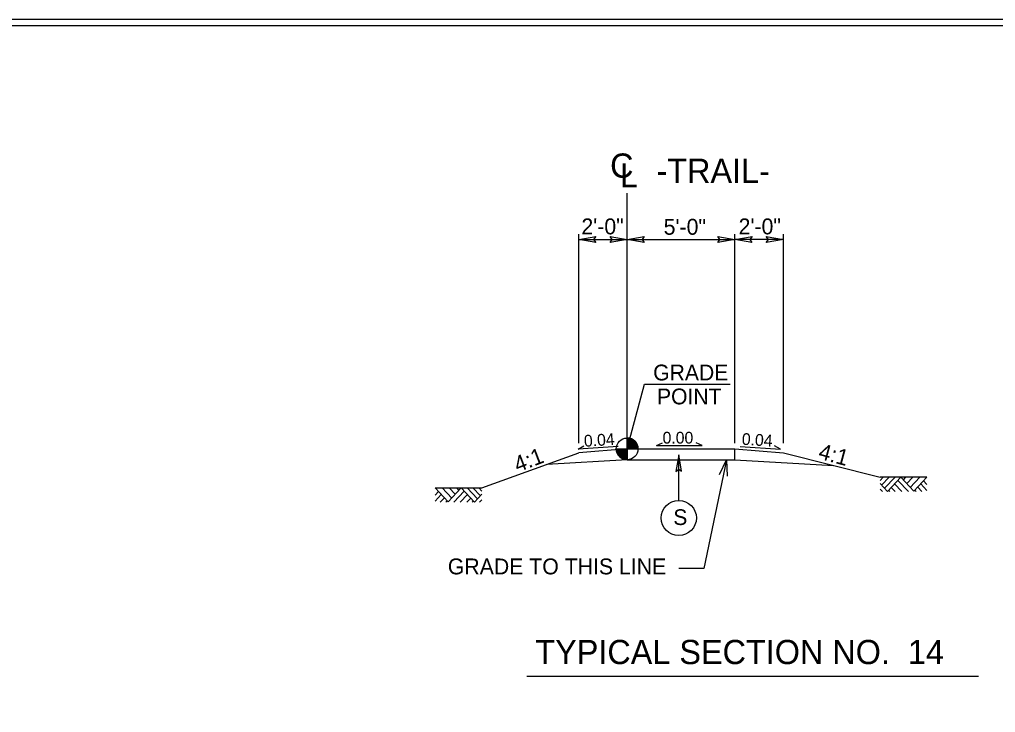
# Model space of a CAD drawing. Extents: x 1901670 to 1902225, y 193498 to 194278.
# Drawn here: x 1902063.51 to 1902103.81, y 193577.14 to 193605.77 of the extents above; entities that cross this region are included whole.
import ezdxf

# ---------------------------------------------------------------- set-up
doc = ezdxf.new("R2010")
doc.units = 0
for name, color, linetype in [('Old_Level_1', 7, 'Continuous'), ('Old_Level_11', 7, 'Continuous'), ('Old_Level_2', 7, 'Continuous'), ('Old_Level_20', 7, 'Continuous'), ('Prop Dimension', 7, 'Continuous'), ('Sheet Border Standard 30in CELL', 7, 'Continuous'), ('Sheet Plot Border Inside CELL', 7, 'Continuous'), ('Typical Hinge Slope Interstate CELL', 7, 'Continuous'), ('Typical Pavement Slope CELL', 7, 'Continuous'), ('Typical Terminator CELL', 7, 'Continuous'), ('Typical Text Grade Point CELL', 7, 'Continuous')]:
    doc.layers.add(name, color=color, linetype=linetype)

# ---------------------------------------------------------------- blocks, each defined once
blk = doc.blocks.new('TERMINATOR')
at = {"layer": 'Typical Terminator CELL'}
blk.add_lwpolyline([(-0.469, 0.081), (0, 0), (-0.471, -0.083), (-0.411, 0)], close=True, dxfattribs=at)

msp = doc.modelspace()

# ---------------------------------------------------------------- linework, layer by layer
at = {"layer": 'Old_Level_1'}
for p, q in [((1902088.596, 193588.03), (1902088.596, 193598.589)), ((1902086.596, 193588.262), (1902086.596, 193596.908)), ((1902093.046, 193588.262), (1902093.046, 193596.908)), ((1902095.046, 193588.262), (1902095.046, 193596.908)), ((1902086.596, 193596.68), (1902088.596, 193596.68)), ((1902095.046, 193596.68), (1902093.046, 193596.68)), ((1902088.596, 193588.03), (1902088.596, 193588.48)), ((1902086.569, 193588.017), (1902086.811, 193588.151)), ((1902088.228, 193588.125), (1902086.569, 193588.017)), ((1902088.596, 193588.03), (1902086.596, 193587.864)), ((1902088.146, 193588.03), (1902088.596, 193588.03)), ((1902088.595, 193587.58), (1902088.596, 193588.03)), ((1902088.596, 193588.03), (1902088.595, 193587.58)), ((1902088.596, 193587.585), (1902088.596, 193588.03)), ((1902089.046, 193588.03), (1902088.596, 193588.03)), ((1902088.596, 193588.03), (1902093.046, 193588.03)), ((1902089.81, 193588.167), (1902090.059, 193588.286)), ((1902089.81, 193588.167), (1902091.701, 193588.167)), ((1902090.039, 193588.167), (1902091.701, 193588.167)), ((1902091.701, 193588.167), (1902091.451, 193588.286)), ((1902093.046, 193587.585), (1902093.046, 193588.03)), ((1902093.046, 193588.03), (1902095.046, 193587.864)), ((1902093.267, 193588.125), (1902094.925, 193588.017)), ((1902094.925, 193588.017), (1902094.684, 193588.151)), ((1902088.596, 193587.585), (1902085.28, 193587.39)), ((1902088.596, 193587.585), (1902088.608, 193587.585)), ((1902088.596, 193587.585), (1902093.046, 193587.585)), ((1902093.046, 193587.585), (1902097.122, 193587.345)), ((1902095.046, 193587.864), (1902099.046, 193586.864)), ((1902099.172, 193586.864), (1902099.046, 193586.728)), ((1902099.41, 193586.864), (1902099.102, 193586.534)), ((1902099.657, 193586.864), (1902099.226, 193586.402)), ((1902099.895, 193586.863), (1902099.346, 193586.273)), ((1902100.208, 193586.267), (1902099.773, 193586.732)), ((1902100.438, 193586.28), (1902099.895, 193586.863)), ((1902100.091, 193586.864), (1902099.993, 193586.758)), ((1902100.389, 193586.864), (1902100.142, 193586.597)), ((1902100.684, 193586.864), (1902100.289, 193586.439)), ((1902100.975, 193586.858), (1902100.438, 193586.28)), ((1902100.975, 193586.56), (1902100.837, 193586.709)), ((1902080.667, 193586.417), (1902081.204, 193585.839)), ((1902080.957, 193586.423), (1902081.352, 193585.998)), ((1902081.204, 193585.839), (1902081.746, 193586.422)), ((1902081.252, 193586.423), (1902081.499, 193586.156)), ((1902081.55, 193586.423), (1902081.649, 193586.317)), ((1902081.746, 193586.422), (1902082.296, 193585.832)), ((1902081.985, 193586.423), (1902082.415, 193585.961)), ((1902082.232, 193586.423), (1902082.539, 193586.093)), ((1902082.47, 193586.423), (1902082.596, 193586.287)), ((1902099.346, 193586.273), (1902099.046, 193586.595)), ((1902099.145, 193586.267), (1902099.046, 193586.373)), ((1902099.443, 193586.267), (1902099.392, 193586.321)), ((1902099.662, 193586.267), (1902099.501, 193586.439)), ((1902099.933, 193586.267), (1902099.636, 193586.585)), ((1902100.53, 193586.267), (1902100.478, 193586.323)), ((1902100.761, 193586.267), (1902100.593, 193586.447)), ((1902100.975, 193586.313), (1902100.721, 193586.585)), ((1902080.667, 193586.119), (1902080.805, 193586.268)), ((1902080.667, 193585.872), (1902080.921, 193586.144)), ((1902080.881, 193585.826), (1902081.049, 193586.006)), ((1902081.434, 193585.826), (1902081.869, 193586.291)), ((1902081.708, 193585.826), (1902082.005, 193586.144)), ((1902081.98, 193585.826), (1902082.141, 193585.998)), ((1902082.296, 193585.832), (1902082.596, 193586.154)), ((1902082.496, 193585.826), (1902082.596, 193585.932)), ((1902081.111, 193585.826), (1902081.164, 193585.882)), ((1902082.199, 193585.826), (1902082.25, 193585.88))]:
    msp.add_line(p, q, dxfattribs=at)
for points in [[(1902088.6, 193588.48), (1902088.6, 193588.48), (1902088.6, 193588.03)], [(1902088.609, 193588.48), (1902088.609, 193588.03)], [(1902088.618, 193588.479), (1902088.618, 193588.03)], [(1902088.627, 193588.479), (1902088.627, 193588.03)], [(1902088.636, 193588.478), (1902088.636, 193588.03)], [(1902088.645, 193588.477), (1902088.645, 193588.03)], [(1902088.654, 193588.476), (1902088.654, 193588.03)], [(1902088.663, 193588.475), (1902088.663, 193588.03)], [(1902088.672, 193588.474), (1902088.672, 193588.03)], [(1902088.681, 193588.472), (1902088.681, 193588.03)], [(1902088.69, 193588.47), (1902088.69, 193588.03)], [(1902088.699, 193588.468), (1902088.699, 193588.03)], [(1902088.708, 193588.466), (1902088.708, 193588.03)], [(1902088.717, 193588.463), (1902088.717, 193588.03)], [(1902088.726, 193588.461), (1902088.726, 193588.03)], [(1902088.735, 193588.458), (1902088.735, 193588.03)], [(1902088.744, 193588.455), (1902088.744, 193588.03)], [(1902088.753, 193588.452), (1902088.753, 193588.03)], [(1902088.762, 193588.448), (1902088.762, 193588.03)], [(1902088.771, 193588.444), (1902088.771, 193588.03)], [(1902088.78, 193588.44), (1902088.78, 193588.03)], [(1902088.789, 193588.436), (1902088.789, 193588.03)], [(1902088.798, 193588.432), (1902088.798, 193588.03)], [(1902088.807, 193588.427), (1902088.807, 193588.03)], [(1902088.816, 193588.422), (1902088.816, 193588.03)], [(1902088.825, 193588.417), (1902088.825, 193588.03)], [(1902088.834, 193588.412), (1902088.834, 193588.03)], [(1902088.843, 193588.406), (1902088.843, 193588.03)], [(1902088.852, 193588.4), (1902088.852, 193588.03)], [(1902088.861, 193588.393), (1902088.861, 193588.03)], [(1902088.87, 193588.387), (1902088.87, 193588.03)], [(1902088.879, 193588.38), (1902088.879, 193588.03)], [(1902088.888, 193588.372), (1902088.888, 193588.03)], [(1902088.897, 193588.364), (1902088.897, 193588.03)], [(1902088.906, 193588.356), (1902088.906, 193588.03)], [(1902088.915, 193588.347), (1902088.915, 193588.03)], [(1902088.924, 193588.338), (1902088.924, 193588.03)], [(1902088.933, 193588.328), (1902088.933, 193588.03)], [(1902088.942, 193588.317), (1902088.942, 193588.03)], [(1902088.148, 193588.03), (1902088.148, 193587.981)], [(1902088.157, 193588.03), (1902088.157, 193587.928)], [(1902088.166, 193588.03), (1902088.166, 193587.896)], [(1902088.175, 193588.03), (1902088.175, 193587.869)], [(1902088.184, 193588.03), (1902088.184, 193587.848)], [(1902088.193, 193588.03), (1902088.193, 193587.829)], [(1902088.202, 193588.03), (1902088.202, 193587.812)], [(1902088.211, 193588.03), (1902088.211, 193587.796)], [(1902088.22, 193588.03), (1902088.22, 193587.782)], [(1902088.229, 193588.03), (1902088.229, 193587.769)], [(1902088.238, 193588.03), (1902088.238, 193587.757)], [(1902088.247, 193588.03), (1902088.247, 193587.746)], [(1902088.256, 193588.03), (1902088.256, 193587.735)], [(1902088.265, 193588.03), (1902088.265, 193587.725)], [(1902088.274, 193588.03), (1902088.274, 193587.715)], [(1902088.283, 193588.03), (1902088.283, 193587.706)], [(1902088.292, 193588.03), (1902088.292, 193587.698)], [(1902088.301, 193588.03), (1902088.301, 193587.69)], [(1902088.31, 193588.03), (1902088.31, 193587.682)], [(1902088.319, 193588.03), (1902088.319, 193587.675)], [(1902088.328, 193588.03), (1902088.328, 193587.668)], [(1902088.337, 193588.03), (1902088.337, 193587.662)], [(1902088.346, 193588.03), (1902088.346, 193587.656)], [(1902088.355, 193588.03), (1902088.355, 193587.65)], [(1902088.364, 193588.03), (1902088.364, 193587.644)], [(1902088.373, 193588.03), (1902088.373, 193587.639)], [(1902088.382, 193588.03), (1902088.382, 193587.634)], [(1902088.391, 193588.03), (1902088.391, 193587.629)], [(1902088.4, 193588.03), (1902088.4, 193587.625)], [(1902088.409, 193588.03), (1902088.409, 193587.621)], [(1902088.418, 193588.03), (1902088.418, 193587.617)], [(1902088.427, 193588.03), (1902088.427, 193587.613)], [(1902088.436, 193588.03), (1902088.436, 193587.609)], [(1902088.445, 193588.03), (1902088.445, 193587.606)], [(1902088.454, 193588.03), (1902088.454, 193587.603)], [(1902088.463, 193588.03), (1902088.463, 193587.6)], [(1902088.472, 193588.03), (1902088.472, 193587.598)], [(1902088.481, 193588.03), (1902088.481, 193587.595)], [(1902088.49, 193588.03), (1902088.49, 193587.593)], [(1902088.499, 193588.03), (1902088.499, 193587.591)], [(1902088.508, 193588.03), (1902088.508, 193587.589)], [(1902088.517, 193588.03), (1902088.517, 193587.587)], [(1902088.526, 193588.03), (1902088.526, 193587.586)], [(1902088.535, 193588.03), (1902088.535, 193587.584)], [(1902088.544, 193588.03), (1902088.544, 193587.583)], [(1902088.553, 193588.03), (1902088.553, 193587.582)], [(1902088.562, 193588.03), (1902088.562, 193587.581)], [(1902088.571, 193588.03), (1902088.571, 193587.581)], [(1902088.58, 193588.03), (1902088.58, 193587.58)], [(1902088.589, 193588.03), (1902088.589, 193587.58), (1902088.589, 193587.58)], [(1902088.951, 193588.306), (1902088.951, 193588.03)], [(1902088.96, 193588.294), (1902088.96, 193588.03)], [(1902088.969, 193588.281), (1902088.969, 193588.03)], [(1902088.978, 193588.267), (1902088.978, 193588.03)], [(1902088.987, 193588.252), (1902088.987, 193588.03)], [(1902088.996, 193588.236), (1902088.996, 193588.03)], [(1902089.005, 193588.217), (1902089.005, 193588.03)], [(1902089.014, 193588.196), (1902089.014, 193588.03)], [(1902089.023, 193588.171), (1902089.023, 193588.03)], [(1902089.032, 193588.14), (1902089.032, 193588.03)], [(1902089.041, 193588.094), (1902089.041, 193588.03)], [(1902092.7, 193587.585), (1902091.76, 193583.093), (1902090.736, 193583.093)], [(1902092.405, 193586.97), (1902092.699, 193587.579), (1902092.726, 193586.904)], [(1902100.975, 193586.864), (1902099.046, 193586.864)], [(1902080.667, 193586.423), (1902082.596, 193586.423)]]:
    msp.add_lwpolyline(points, dxfattribs=at)
msp.add_circle((1902088.595, 193588.03), 0.45, dxfattribs=at)
for start, end in [(359.9905, 89.9905), (179.9905, 269.9905)]:
    msp.add_arc((1902088.595, 193588.03), 0.45, start, end, dxfattribs=at)
at = {"layer": 'Old_Level_11'}
for p, q in [((1902090.731, 193585.904), (1902090.731, 193587.779)), ((1902084.452, 193578.646), (1902101.078, 193578.646)), ((1902085.452, 193578.646), (1902103.098, 193578.646))]:
    msp.add_line(p, q, dxfattribs=at)
msp.add_lwpolyline([(1902090.846, 193587.107), (1902090.731, 193587.779), (1902090.611, 193587.103), (1902090.731, 193587.189)], close=True, dxfattribs=at)
msp.add_circle((1902090.73, 193585.179), 0.725, dxfattribs=at)
at = {"layer": 'Prop Dimension'}
msp.add_line((1902088.596, 193596.68), (1902093.046, 193596.68), dxfattribs=at)
at = {"layer": 'Sheet Border Standard 30in CELL'}
msp.add_lwpolyline([(1902132.544, 193605.514), (1901982.544, 193605.514), (1901982.544, 193500.514), (1902132.544, 193500.514)], close=True, dxfattribs=at)
at = {"layer": 'Sheet Plot Border Inside CELL'}
msp.add_lwpolyline([(1902133.794, 193605.769), (1901967.144, 193605.769), (1901967.144, 193500.259), (1902133.794, 193500.259)], close=True, dxfattribs=at)
at = {"layer": 'Typical Pavement Slope CELL'}
msp.add_line((1902082.596, 193586.423), (1902086.596, 193587.864), dxfattribs=at)
at = {"layer": 'Typical Text Grade Point CELL'}
for p, q in [((1902088.596, 193588.03), (1902089.308, 193590.703)), ((1902089.308, 193590.703), (1902092.846, 193590.703))]:
    msp.add_line(p, q, dxfattribs=at)

# ---------------------------------------------------------------- block references
at = {"layer": 'Prop Dimension', "xscale": 1.5, "yscale": 1.5, "rotation": 180}
for p in [(1902086.596, 193596.68), (1902088.596, 193596.68), (1902093.046, 193596.68)]:
    msp.add_blockref('TERMINATOR', p, dxfattribs=at)
at = {"layer": 'Prop Dimension', "xscale": 1.5, "yscale": 1.5}
for p in [(1902088.596, 193596.68), (1902093.046, 193596.68), (1902095.046, 193596.68)]:
    msp.add_blockref('TERMINATOR', p, dxfattribs=at)

# ---------------------------------------------------------------- texts
at = {"layer": 'Old_Level_1'}
msp.add_text('4:1', height=0.656, rotation=20.8342, dxfattribs=at).set_placement((1902084.075, 193587.053))
msp.add_text('GRADE TO THIS LINE', height=0.656, dxfattribs=at).set_placement((1902081.193, 193582.847))
at = {"layer": 'Old_Level_11'}
msp.add_text('TYPICAL SECTION NO.  14', height=1, dxfattribs=at).set_placement((1902084.808, 193579.14))
at = {"layer": 'Old_Level_2'}
msp.add_text('C', height=1, dxfattribs=at).set_placement((1902087.894, 193599.235))
for s, height, rotation, p in [('-TRAIL-', 1, 359.9469, (1902089.81, 193599.022)), ('L', 1, 359.9469, (1902088.296, 193598.831)), ('0.00', 0.4866, 0.0114, (1902090.06, 193588.25)), ('0.04', 0.4866, 3.7166, (1902086.829, 193588.116)), ('0.04', 0.4866, 356.2834, (1902093.32, 193588.204))]:
    msp.add_text(s, height=height, rotation=rotation, dxfattribs=at).set_placement(p)
at = {"layer": 'Old_Level_20'}
msp.add_text('S', height=0.649, dxfattribs=at).set_placement((1902090.504, 193584.886))
at = {"layer": 'Prop Dimension'}
for s, p in [('2\'-0" ', (1902086.708, 193596.894)), ('5\'-0" ', (1902090.105, 193596.878)), ('2\'-0" ', (1902093.199, 193596.894))]:
    msp.add_text(s, height=0.656, dxfattribs=at).set_placement(p)
at = {"layer": 'Typical Hinge Slope Interstate CELL'}
msp.add_text('4:1', height=0.656, rotation=345.0066, dxfattribs=at).set_placement((1902096.456, 193587.636))
at = {"layer": 'Typical Text Grade Point CELL'}
for s, p in [('GRADE', (1902089.672, 193590.86)), ('POINT', (1902089.829, 193589.871))]:
    msp.add_text(s, height=0.6525, dxfattribs=at).set_placement(p)

doc.saveas('drawing.dxf')
